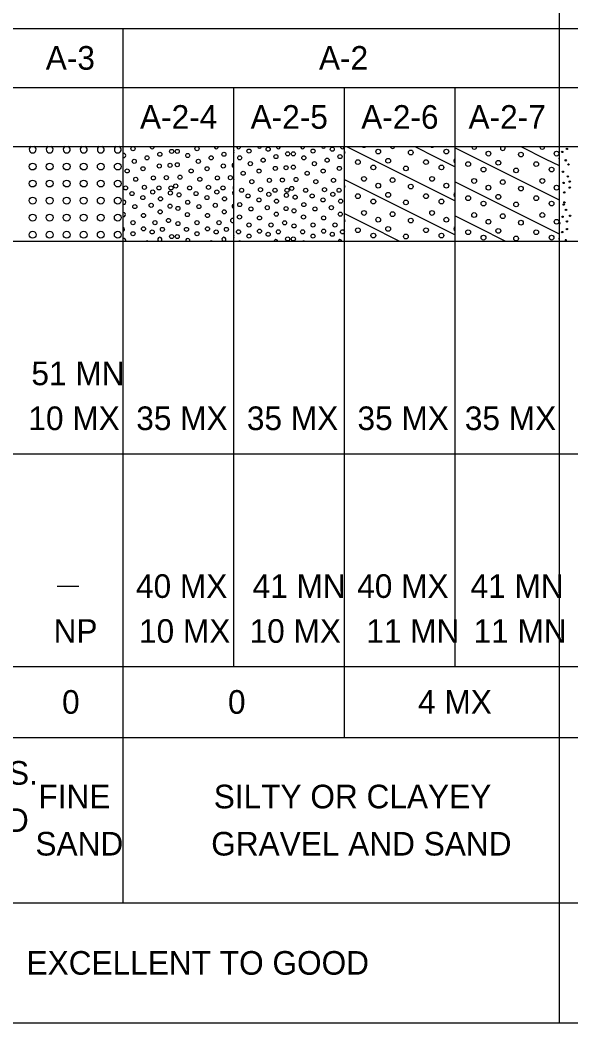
# Model space of a CAD drawing. Extents: x 278618 to 280654, y 171155 to 171855.
# Drawn here: x 280482.47 to 280492.58, y 171593.09 to 171611.5 of the extents above; entities that cross this region are included whole.
import ezdxf

# ---------------------------------------------------------------- set-up
doc = ezdxf.new("R2010")
doc.units = 0
doc.layers.add('Geotech Sheets and Borders Cell', color=7, linetype='Continuous')

msp = doc.modelspace()

# ---------------------------------------------------------------- linework, layer by layer
at = {"layer": 'Geotech Sheets and Borders Cell'}
for p, q in [((280492.367, 171613.515), (280492.367, 171593.093)), ((280474.148, 171611.346), (280511.888, 171611.346)), ((280484.368, 171595.296), (280484.368, 171611.346)), ((280478.269, 171610.262), (280500.609, 171610.262)), ((280486.398, 171599.634), (280486.398, 171610.262)), ((280488.428, 171598.333), (280488.428, 171610.262)), ((280490.459, 171599.634), (280490.459, 171610.262)), ((280474.148, 171609.177), (280511.888, 171609.177)), ((280488.466, 171609.177), (280488.854, 171608.983)), ((280489.716, 171609.177), (280490.104, 171608.983)), ((280490.459, 171609.155), (280490.876, 171608.946)), ((280491.664, 171609.177), (280492.126, 171608.946)), ((280488.854, 171608.983), (280490.104, 171608.358)), ((280490.104, 171608.983), (280490.459, 171608.806)), ((280490.876, 171608.946), (280492.126, 171608.321)), ((280492.126, 171608.946), (280492.367, 171608.826)), ((280488.428, 171608.571), (280488.854, 171608.358)), ((280490.459, 171608.53), (280490.876, 171608.321)), ((280488.854, 171608.358), (280490.104, 171607.733)), ((280490.104, 171608.358), (280490.459, 171608.181)), ((280490.876, 171608.321), (280492.126, 171607.696)), ((280492.126, 171608.321), (280492.367, 171608.201)), ((280488.428, 171607.946), (280488.854, 171607.733)), ((280490.459, 171607.905), (280490.876, 171607.696)), ((280488.854, 171607.733), (280489.436, 171607.442)), ((280490.104, 171607.733), (280490.459, 171607.556)), ((280490.876, 171607.696), (280491.384, 171607.442)), ((280492.126, 171607.696), (280492.367, 171607.576)), ((280474.148, 171607.442), (280511.888, 171607.442)), ((280474.148, 171603.538), (280511.888, 171603.538)), ((280483.154, 171601.11), (280483.553, 171601.11)), ((280474.148, 171599.634), (280500.609, 171599.634)), ((280474.148, 171598.333), (280500.609, 171598.333)), ((280474.148, 171595.296), (280511.888, 171595.296)), ((280474.148, 171593.093), (280511.888, 171593.093))]:
    msp.add_line(p, q, dxfattribs=at)
for centre, radius in [((280484.545, 171609.138), 0.0375), ((280484.804, 171608.97), 0.0375), ((280485.039, 171609.035), 0.0375), ((280485.255, 171609.087), 0.0375), ((280485.358, 171609.087), 0.0375), ((280485.551, 171609.013), 0.0375), ((280485.721, 171609.138), 0.0375), ((280485.98, 171608.97), 0.0375), ((280486.215, 171609.035), 0.0375), ((280486.505, 171608.969), 0.0375), ((280486.675, 171609.094), 0.0375), ((280487.027, 171609.128), 0.0375), ((280487.169, 171608.992), 0.0375), ((280487.385, 171609.043), 0.0375), ((280487.488, 171609.043), 0.0375), ((280487.681, 171608.969), 0.0375), ((280487.851, 171609.094), 0.0375), ((280488.203, 171609.128), 0.0375), ((280488.345, 171608.992), 0.0375), ((280489.047, 171609.084), 0.0437), ((280489.644, 171609.068), 0.0437), ((280490.297, 171609.084), 0.0437), ((280491.07, 171609.047), 0.0437), ((280491.666, 171609.03), 0.0437), ((280492.32, 171609.047), 0.0437), ((280492.425, 171609.077), 0.0125), ((280492.511, 171609.134), 0.0125), ((280482.704, 171608.809), 0.0625), ((280483.016, 171608.809), 0.0625), ((280483.329, 171608.809), 0.0625), ((280483.641, 171608.809), 0.0625), ((280483.954, 171608.809), 0.0625), ((280484.266, 171608.809), 0.0625), ((280484.569, 171608.905), 0.0375), ((280485.028, 171608.82), 0.0375), ((280485.226, 171608.832), 0.0375), ((280485.358, 171608.843), 0.0375), ((280485.745, 171608.905), 0.0375), ((280486.203, 171608.82), 0.0375), ((280486.699, 171608.862), 0.0375), ((280486.934, 171608.926), 0.0375), ((280487.158, 171608.776), 0.0375), ((280487.356, 171608.788), 0.0375), ((280487.488, 171608.799), 0.0375), ((280487.875, 171608.862), 0.0375), ((280488.11, 171608.926), 0.0375), ((280488.333, 171608.776), 0.0375), ((280488.674, 171608.891), 0.0437), ((280488.957, 171608.793), 0.0437), ((280489.229, 171608.916), 0.0437), ((280489.554, 171608.776), 0.0437), ((280489.924, 171608.891), 0.0437), ((280490.207, 171608.793), 0.0437), ((280490.697, 171608.854), 0.0437), ((280491.251, 171608.879), 0.0437), ((280491.947, 171608.854), 0.0437), ((280492.488, 171608.924), 0.0125), ((280492.539, 171608.85), 0.0125), ((280484.438, 171608.729), 0.0375), ((280484.73, 171608.77), 0.0375), ((280484.92, 171608.601), 0.0375), ((280485.158, 171608.605), 0.0375), ((280485.409, 171608.615), 0.0375), ((280485.613, 171608.729), 0.0375), ((280485.906, 171608.77), 0.0375), ((280486.095, 171608.601), 0.0375), ((280486.334, 171608.605), 0.0375), ((280486.568, 171608.686), 0.0375), ((280486.86, 171608.727), 0.0375), ((280487.743, 171608.686), 0.0375), ((280488.036, 171608.727), 0.0375), ((280490.979, 171608.755), 0.0437), ((280491.577, 171608.739), 0.0437), ((280492.229, 171608.755), 0.0437), ((280492.436, 171608.714), 0.0125), ((280492.527, 171608.629), 0.0125), ((280482.704, 171608.497), 0.0625), ((280483.016, 171608.497), 0.0625), ((280483.329, 171608.497), 0.0625), ((280483.641, 171608.497), 0.0625), ((280483.954, 171608.497), 0.0625), ((280484.266, 171608.497), 0.0625), ((280484.409, 171608.417), 0.0375), ((280484.596, 171608.576), 0.0375), ((280484.755, 171608.428), 0.0375), ((280485.022, 171608.417), 0.0375), ((280485.243, 171608.417), 0.0375), ((280485.33, 171608.452), 0.0375), ((280485.585, 171608.417), 0.0375), ((280485.772, 171608.576), 0.0375), ((280485.931, 171608.428), 0.0375), ((280486.198, 171608.417), 0.0375), ((280486.726, 171608.532), 0.0375), ((280487.05, 171608.557), 0.0375), ((280487.288, 171608.561), 0.0375), ((280487.46, 171608.408), 0.0375), ((280487.539, 171608.572), 0.0375), ((280487.902, 171608.532), 0.0375), ((280488.225, 171608.557), 0.0375), ((280488.785, 171608.583), 0.0437), ((280489.047, 171608.459), 0.0437), ((280489.31, 171608.561), 0.0437), ((280489.644, 171608.443), 0.0437), ((280490.035, 171608.583), 0.0437), ((280490.297, 171608.459), 0.0437), ((280490.808, 171608.545), 0.0437), ((280491.07, 171608.422), 0.0437), ((280491.333, 171608.524), 0.0437), ((280491.666, 171608.405), 0.0437), ((280492.058, 171608.545), 0.0437), ((280492.32, 171608.422), 0.0437), ((280492.448, 171608.509), 0.0125), ((280492.561, 171608.533), 0.0125), ((280484.528, 171608.314), 0.0375), ((280484.727, 171608.24), 0.0375), ((280484.908, 171608.342), 0.0375), ((280485.232, 171608.325), 0.0375), ((280485.392, 171608.29), 0.0375), ((280485.704, 171608.314), 0.0375), ((280485.903, 171608.24), 0.0375), ((280486.084, 171608.342), 0.0375), ((280486.539, 171608.374), 0.0375), ((280486.658, 171608.271), 0.0375), ((280486.885, 171608.385), 0.0375), ((280487.038, 171608.299), 0.0375), ((280487.152, 171608.374), 0.0375), ((280487.362, 171608.282), 0.0375), ((280487.373, 171608.374), 0.0375), ((280487.522, 171608.247), 0.0375), ((280487.715, 171608.374), 0.0375), ((280487.834, 171608.271), 0.0375), ((280488.061, 171608.385), 0.0375), ((280488.214, 171608.299), 0.0375), ((280488.328, 171608.374), 0.0375), ((280488.674, 171608.266), 0.0437), ((280489.229, 171608.291), 0.0437), ((280489.924, 171608.266), 0.0437), ((280490.697, 171608.229), 0.0437), ((280491.251, 171608.254), 0.0437), ((280491.947, 171608.229), 0.0437), ((280492.46, 171608.334), 0.0125), ((280492.561, 171608.424), 0.0125), ((280482.704, 171608.184), 0.0625), ((280483.016, 171608.184), 0.0625), ((280483.329, 171608.184), 0.0625), ((280483.641, 171608.184), 0.0625), ((280483.954, 171608.184), 0.0625), ((280484.266, 171608.184), 0.0625), ((280484.58, 171608.075), 0.0375), ((280484.88, 171608.098), 0.0375), ((280485.05, 171608.217), 0.0375), ((280485.226, 171608.082), 0.0375), ((280485.37, 171608.041), 0.0375), ((280485.551, 171608.154), 0.0375), ((280485.755, 171608.075), 0.0375), ((280486.056, 171608.098), 0.0375), ((280486.226, 171608.217), 0.0375), ((280486.505, 171608.111), 0.0375), ((280486.857, 171608.197), 0.0375), ((280487.01, 171608.055), 0.0375), ((280487.18, 171608.174), 0.0375), ((280487.681, 171608.111), 0.0375), ((280488.033, 171608.197), 0.0375), ((280488.186, 171608.055), 0.0375), ((280488.356, 171608.174), 0.0375), ((280488.957, 171608.168), 0.0437), ((280489.554, 171608.151), 0.0437), ((280490.207, 171608.168), 0.0437), ((280490.979, 171608.13), 0.0437), ((280491.577, 171608.114), 0.0437), ((280492.229, 171608.13), 0.0437), ((280492.453, 171608.111), 0.0125), ((280492.465, 171608.152), 0.0125), ((280482.704, 171607.872), 0.0625), ((280483.016, 171607.872), 0.0625), ((280483.329, 171607.872), 0.0625), ((280483.641, 171607.872), 0.0625), ((280483.954, 171607.872), 0.0625), ((280484.266, 171607.872), 0.0625), ((280484.738, 171607.911), 0.0375), ((280485.045, 171607.979), 0.0375), ((280485.545, 171607.928), 0.0375), ((280485.914, 171607.911), 0.0375), ((280486.22, 171607.979), 0.0375), ((280486.5, 171607.884), 0.0375), ((280486.71, 171608.032), 0.0375), ((280486.868, 171607.867), 0.0375), ((280487.175, 171607.936), 0.0375), ((280487.356, 171608.038), 0.0375), ((280487.5, 171607.997), 0.0375), ((280487.675, 171607.884), 0.0375), ((280487.885, 171608.032), 0.0375), ((280488.044, 171607.867), 0.0375), ((280488.35, 171607.936), 0.0375), ((280488.785, 171607.958), 0.0437), ((280489.31, 171607.936), 0.0437), ((280490.035, 171607.958), 0.0437), ((280490.808, 171607.92), 0.0437), ((280491.333, 171607.899), 0.0437), ((280492.058, 171607.92), 0.0437), ((280492.431, 171607.889), 0.0125), ((280492.493, 171608.014), 0.0125), ((280492.567, 171607.906), 0.0125), ((280484.545, 171607.78), 0.0375), ((280484.948, 171607.78), 0.0375), ((280485.198, 171607.82), 0.0375), ((280485.37, 171607.763), 0.0375), ((280485.721, 171607.78), 0.0375), ((280486.124, 171607.78), 0.0375), ((280486.675, 171607.737), 0.0375), ((280487.078, 171607.737), 0.0375), ((280487.328, 171607.777), 0.0375), ((280487.5, 171607.72), 0.0375), ((280487.851, 171607.737), 0.0375), ((280488.254, 171607.737), 0.0375), ((280489.047, 171607.834), 0.0437), ((280489.229, 171607.666), 0.0437), ((280489.644, 171607.818), 0.0437), ((280490.297, 171607.834), 0.0437), ((280491.07, 171607.797), 0.0437), ((280491.666, 171607.78), 0.0437), ((280492.32, 171607.797), 0.0437), ((280492.51, 171607.804), 0.0125), ((280482.704, 171607.559), 0.0625), ((280483.016, 171607.559), 0.0625), ((280483.329, 171607.559), 0.0625), ((280483.641, 171607.559), 0.0625), ((280483.954, 171607.559), 0.0625), ((280484.266, 171607.559), 0.0625), ((280484.545, 171607.577), 0.0375), ((280484.738, 171607.667), 0.0375), ((280484.897, 171607.61), 0.0375), ((280485.085, 171607.656), 0.0375), ((280485.255, 171607.525), 0.0375), ((280485.358, 171607.525), 0.0375), ((280485.528, 171607.656), 0.0375), ((280485.721, 171607.577), 0.0375), ((280485.914, 171607.667), 0.0375), ((280486.073, 171607.61), 0.0375), ((280486.26, 171607.656), 0.0375), ((280486.483, 171607.612), 0.0375), ((280486.675, 171607.533), 0.0375), ((280486.868, 171607.624), 0.0375), ((280487.027, 171607.567), 0.0375), ((280487.215, 171607.612), 0.0375), ((280487.658, 171607.612), 0.0375), ((280487.851, 171607.533), 0.0375), ((280488.044, 171607.624), 0.0375), ((280488.203, 171607.567), 0.0375), ((280488.39, 171607.612), 0.0375), ((280488.674, 171607.641), 0.0437), ((280488.957, 171607.543), 0.0437), ((280489.554, 171607.526), 0.0437), ((280489.924, 171607.641), 0.0437), ((280490.207, 171607.543), 0.0437), ((280490.697, 171607.604), 0.0437), ((280490.979, 171607.505), 0.0437), ((280491.251, 171607.629), 0.0437), ((280491.577, 171607.489), 0.0437), ((280491.947, 171607.604), 0.0437), ((280492.229, 171607.505), 0.0437), ((280492.425, 171607.606), 0.0125), ((280492.511, 171607.663), 0.0125), ((280487.385, 171607.482), 0.0375), ((280487.488, 171607.482), 0.0375)]:
    msp.add_circle(centre, radius, dxfattribs=at)
for centre, radius, start, end in [((280482.704, 171609.122), 0.0625, 117.2937, 62.7063), ((280483.016, 171609.122), 0.0625, 117.2937, 62.7063), ((280483.329, 171609.122), 0.0625, 117.2937, 62.7063), ((280483.641, 171609.122), 0.0625, 117.2937, 62.7063), ((280483.954, 171609.122), 0.0625, 117.2937, 62.7063), ((280484.266, 171609.122), 0.0625, 117.2937, 62.7063), ((280484.375, 171609.013), 0.0375, 259.1391, 100.8609), ((280484.897, 171609.172), 0.0375, 171.147, 8.853), ((280486.073, 171609.172), 0.0375, 171.147, 8.853), ((280486.43, 171609.087), 0.0375, 148.7579, 211.2421), ((280486.483, 171609.174), 0.0375, 174.4692, 5.5308), ((280486.868, 171609.185), 0.0375, 191.7487, 348.2513), ((280487.215, 171609.174), 0.0375, 174.4692, 5.5308), ((280487.658, 171609.174), 0.0375, 174.4692, 5.5308), ((280488.044, 171609.185), 0.0375, 191.7487, 348.2513), ((280488.39, 171609.174), 0.0375, 174.4692, 5.5308), ((280488.394, 171609.068), 0.0437, 322.3805, 37.6195), ((280488.785, 171609.208), 0.0437, 223.6373, 316.3627), ((280489.31, 171609.186), 0.0437, 191.793, 348.207), ((280490.035, 171609.208), 0.0437, 223.6373, 316.3627), ((280490.416, 171609.03), 0.0437, 350.9144, 9.0856), ((280490.808, 171609.17), 0.0437, 170.7511, 9.2489), ((280491.333, 171609.149), 0.0437, 139.7264, 40.2736), ((280492.058, 171609.17), 0.0437, 170.7511, 9.2489), ((280486.402, 171608.832), 0.0375, 96.0262, 263.9738), ((280490.479, 171608.916), 0.0437, 116.2386, 243.7614), ((280492.357, 171608.958), 0.0125, 324.1084, 35.8916), ((280492.363, 171608.816), 0.0125, 291.108, 68.892), ((280486.419, 171608.417), 0.0375, 123.7096, 236.2904), ((280486.363, 171608.572), 0.0375, 338.4467, 21.5533), ((280488.464, 171608.561), 0.0375, 162.3921, 197.6079), ((280488.394, 171608.443), 0.0437, 322.3805, 37.6195), ((280486.408, 171608.325), 0.0375, 104.7726, 255.2274), ((280490.479, 171608.291), 0.0437, 116.2386, 243.7614), ((280490.416, 171608.405), 0.0437, 350.9144, 9.0856), ((280492.363, 171608.249), 0.0125, 291.108, 68.892), ((280484.375, 171608.154), 0.0375, 259.1391, 100.8609), ((280486.402, 171608.082), 0.0375, 96.0262, 263.9738), ((280484.37, 171607.928), 0.0375, 267.7979, 92.2021), ((280486.373, 171607.82), 0.0375, 48.5716, 311.4284), ((280488.394, 171607.818), 0.0437, 322.3805, 37.6195), ((280490.416, 171607.78), 0.0437, 350.9144, 9.0856), ((280492.374, 171607.77), 0.0125, 237.325, 122.675), ((280484.353, 171607.656), 0.0375, 294.3038, 65.6962), ((280486.43, 171607.525), 0.0375, 148.7579, 211.2421), ((280490.479, 171607.666), 0.0437, 116.2386, 243.7614), ((280484.375, 171607.452), 0.0375, 345.7476, 100.8609), ((280484.804, 171607.408), 0.0375, 64.663, 115.337), ((280485.039, 171607.474), 0.0375, 302.2, 237.8), ((280485.551, 171607.452), 0.0375, 345.7476, 194.2524), ((280485.98, 171607.408), 0.0375, 64.663, 115.337), ((280486.215, 171607.474), 0.0375, 302.2, 237.8), ((280486.505, 171607.408), 0.0375, 65.917, 114.083), ((280487.169, 171607.431), 0.0375, 18.2374, 161.7626), ((280487.681, 171607.408), 0.0375, 65.917, 114.083), ((280488.345, 171607.431), 0.0375, 18.2374, 161.7626), ((280492.357, 171607.486), 0.0125, 324.1084, 35.8916), ((280492.488, 171607.453), 0.0125, 305.1764, 234.8236)]:
    msp.add_arc(centre, radius, start, end, dxfattribs=at)

# ---------------------------------------------------------------- texts
for s, height, p in [('A-3', 0.4338, (280482.944, 171610.587)), ('A-2', 0.4338, (280487.959, 171610.587)), ('A-2-4', 0.4338, (280484.674, 171609.503)), ('A-2-5', 0.4338, (280486.704, 171609.503)), ('A-2-6', 0.4338, (280488.735, 171609.503)), ('A-2-7', 0.4338, (280490.704, 171609.503)), ('51 MN', 0.4338, (280482.681, 171604.797)), ('10 MX', 0.4338, (280482.626, 171603.973)), ('35 MX', 0.4338, (280484.606, 171603.973)), ('35 MX', 0.4338, (280486.636, 171603.973)), ('35 MX', 0.4338, (280488.666, 171603.973)), ('35 MX', 0.4338, (280490.636, 171603.973)), ('40 MX', 0.4338, (280484.601, 171600.893)), ('41 MN', 0.4338, (280486.741, 171600.893)), ('40 MX', 0.4338, (280488.661, 171600.893)), ('41 MN', 0.4338, (280490.741, 171600.893)), ('NP', 0.4338, (280483.088, 171600.069)), ('10 MX', 0.4338, (280484.656, 171600.069)), ('10 MX', 0.4338, (280486.686, 171600.069)), ('11 MN', 0.4338, (280488.827, 171600.069)), ('11 MN', 0.4338, (280490.796, 171600.069)), ('0', 0.434, (280483.244, 171598.767)), ('0', 0.434, (280486.289, 171598.767)), ('4 MX', 0.4338, (280489.778, 171598.767)), ('STONE FRAGS.', 0.43381, (280478.481, 171597.465)), ('FINE', 0.4338, (280482.81, 171597.031)), ('SILTY OR CLAYEY', 0.43381, (280486.028, 171597.031)), ('GRAVEL, AND', 0.43381, (280478.732, 171596.598)), ('SAND', 0.4338, (280482.755, 171596.165)), ('GRAVEL AND SAND', 0.43381, (280485.981, 171596.165)), ('EXCELLENT TO GOOD', 0.43381, (280482.592, 171593.978))]:
    msp.add_text(s, height=height, dxfattribs=at).set_placement(p)

doc.saveas('drawing.dxf')
